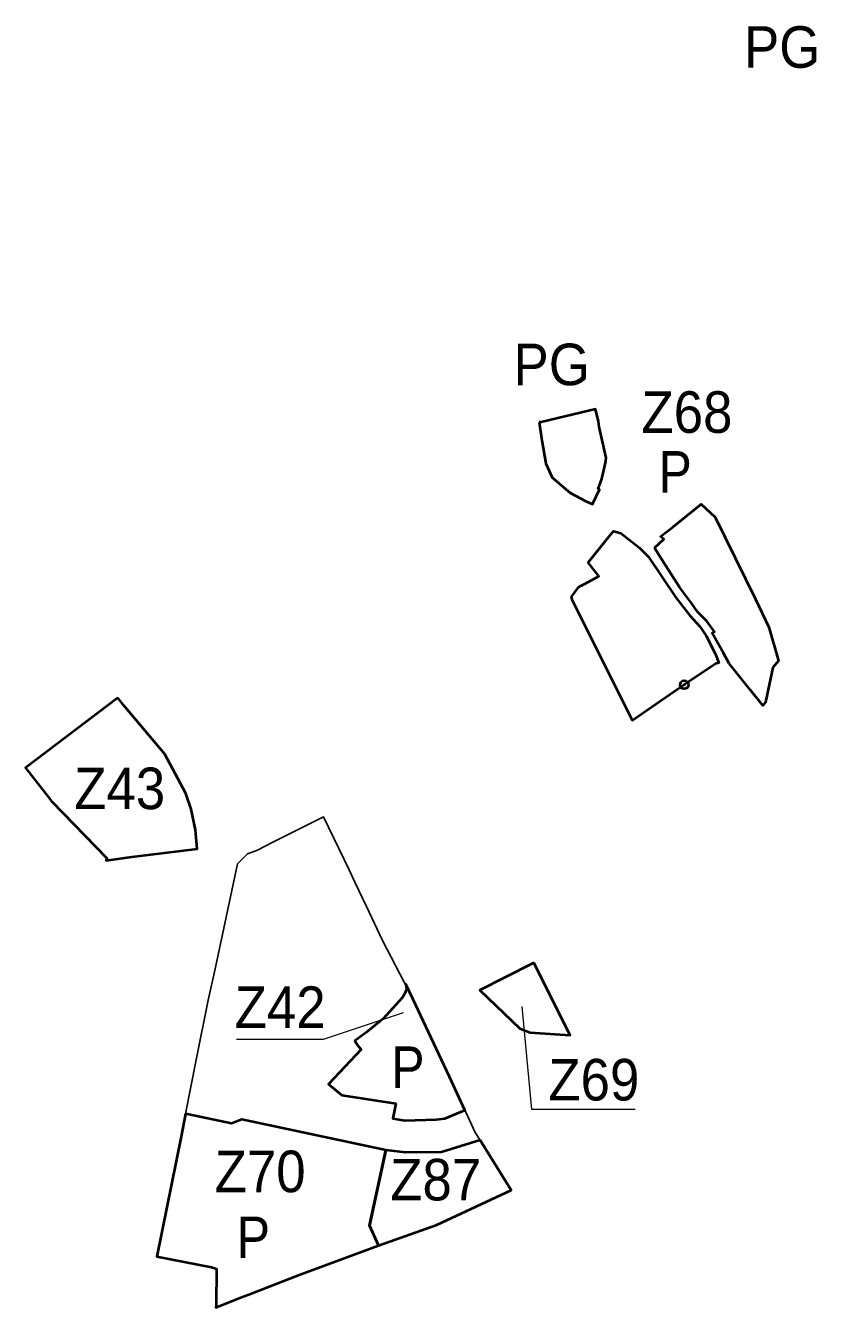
# Model space of a CAD drawing. Extents: x -650276 to -642489, y -1074311 to -1066658.
# Drawn here: x -647280 to -646824, y -1071533 to -1070793 of the extents above; entities that cross this region are included whole.
import ezdxf

# ---------------------------------------------------------------- set-up
doc = ezdxf.new("R2010")
doc.units = 0
doc.header["$LTSCALE"] = 9.6
doc.header["$PDMODE"] = 32
doc.header["$PDSIZE"] = 4.8
for name, color, linetype, lineweight in [('42', 7, 'Continuous', 25), ('44', 7, 'Continuous', 40), ('45', 7, 'Continuous', 40), ('46', 7, 'Continuous', 13), ('60', 7, 'Continuous', 35)]:
    doc.layers.add(name, color=color, linetype=linetype, lineweight=lineweight)

msp = doc.modelspace()

# ---------------------------------------------------------------- linework, layer by layer
at = {"layer": '42'}
msp.add_lwpolyline([(-647187.85, -1071421.58), (-647190.4, -1071434.75), (-647204.42, -1071504.1), (-647172.74, -1071510.15), (-647170.01, -1071511.22), (-647170.18, -1071532.22), (-647170.23, -1071533.44), (-647155.58, -1071527.62), (-647151.28, -1071525.99), (-647123.17, -1071515.01), (-647104.47, -1071508.08), (-647076.46, -1071497.69), (-647042.78, -1071485.76), (-647022.81, -1071476.61), (-646999.77, -1071465.81), (-647017.7, -1071436.79), (-647020.52, -1071432.42), (-647030.23, -1071411.53), (-647035.47, -1071400.31), (-647056.48, -1071355.32), (-647073.98, -1071321.53), (-647083.22, -1071302), (-647090, -1071287.89), (-647093.39, -1071280.83), (-647108.16, -1071250.08), (-647130.76, -1071261.49), (-647137.84, -1071265.06), (-647146.3, -1071269.33), (-647152.09, -1071271.47), (-647157.83, -1071277.35), (-647168.91, -1071329.88), (-647170.63, -1071337.91), (-647174.73, -1071356.1), (-647181.75, -1071390.51)], close=True, dxfattribs=at)
at = {"layer": '44'}
msp.add_line((-647081.488, -1071486.251), (-647076.46, -1071497.69), dxfattribs=at)
for points in [[(-647017.7, -1071436.79), (-647040.089, -1071443.76), (-647060.812, -1071444.006), (-647072.11, -1071442.6), (-647081.488, -1071486.251)], [(-647076.46, -1071497.69), (-647042.78, -1071485.76), (-647022.81, -1071476.61), (-646999.77, -1071465.81), (-647017.7, -1071436.79)]]:
    msp.add_lwpolyline(points, dxfattribs=at)
at = {"layer": '45'}
for points in [[(-646983.66, -1071022.3), (-646982.08, -1071032.76), (-646979.75, -1071046.19), (-646976.03, -1071054.29), (-646965.69, -1071063.05), (-646956.66, -1071067.91), (-646952.75, -1071069.62), (-646948.83, -1071061.12), (-646949.48, -1071060.79), (-646947.41, -1071054.95), (-646945.38, -1071045.82), (-646944.88, -1071042.78), (-646948.89, -1071024.84), (-646949.39, -1071021.83), (-646951.06, -1071014.78), (-646955.09, -1071015.67), (-646982.41, -1071022.23)], [(-646983.66, -1071022.3), (-646982.08, -1071032.76), (-646979.75, -1071046.19), (-646976.03, -1071054.29), (-646965.69, -1071063.05), (-646956.66, -1071067.91), (-646952.75, -1071069.62), (-646948.83, -1071061.12), (-646949.48, -1071060.79), (-646947.41, -1071054.95), (-646945.38, -1071045.82), (-646944.88, -1071042.78), (-646948.89, -1071024.84), (-646949.39, -1071021.83), (-646951.06, -1071014.78), (-646955.09, -1071015.67), (-646982.41, -1071022.23)], [(-646917.04, -1071094.75), (-646911.58, -1071089.9), (-646913.49, -1071088.22), (-646906.17, -1071082.72), (-646890.12, -1071069.67), (-646881.89, -1071077.03), (-646858.769, -1071124.46), (-646850.93, -1071140.54), (-646845.39, -1071159.98), (-646848.58, -1071163.95), (-646852.86, -1071183.98), (-646854.49, -1071185.87), (-646861.58, -1071177.05), (-646873.89, -1071161.58), (-646877.226, -1071155.611), (-646883.63, -1071144.15), (-646882.37, -1071143.39), (-646886.78, -1071137.25), (-646892.11, -1071131.81), (-646895.56, -1071126.84), (-646902.62, -1071117.58), (-646910.53, -1071105.18)], [(-646917.04, -1071094.75), (-646911.58, -1071089.9), (-646913.49, -1071088.22), (-646906.17, -1071082.72), (-646890.12, -1071069.67), (-646881.89, -1071077.03), (-646858.769, -1071124.46), (-646850.93, -1071140.54), (-646845.39, -1071159.98), (-646848.58, -1071163.95), (-646852.86, -1071183.98), (-646854.49, -1071185.87), (-646861.58, -1071177.05), (-646873.89, -1071161.58), (-646877.226, -1071155.611), (-646883.63, -1071144.15), (-646882.37, -1071143.39), (-646886.78, -1071137.25), (-646892.11, -1071131.81), (-646895.56, -1071126.84), (-646902.62, -1071117.58), (-646910.53, -1071105.18)], [(-646921.668, -1071098.861), (-646920.54, -1071099.98), (-646904.64, -1071123.54), (-646896.62, -1071133.93), (-646890.59, -1071140.39), (-646887.07, -1071145.66), (-646881.97, -1071155.84), (-646879.91, -1071161.24), (-646881.68, -1071161.83), (-646899.85, -1071173.89), (-646929.64, -1071194.58), (-646955.2, -1071143.67), (-646964.43, -1071125.3), (-646964.99, -1071123.18), (-646960.72, -1071117.25), (-646957.26, -1071115.61), (-646949.12, -1071111.22), (-646955.39, -1071103.23), (-646943.47, -1071088.69), (-646940.67, -1071085.15), (-646936.51, -1071086.33), (-646925.88, -1071094.68)], [(-646921.668, -1071098.861), (-646920.54, -1071099.98), (-646904.64, -1071123.54), (-646896.62, -1071133.93), (-646890.59, -1071140.39), (-646887.07, -1071145.66), (-646881.97, -1071155.84), (-646879.91, -1071161.24), (-646881.68, -1071161.83), (-646899.85, -1071173.89), (-646929.64, -1071194.58), (-646955.2, -1071143.67), (-646964.43, -1071125.3), (-646964.99, -1071123.18), (-646960.72, -1071117.25), (-646957.26, -1071115.61), (-646949.12, -1071111.22), (-646955.39, -1071103.23), (-646943.47, -1071088.69), (-646940.67, -1071085.15), (-646936.51, -1071086.33), (-646925.88, -1071094.68)], [(-647226.895, -1071181.511), (-647280.14, -1071221.92), (-647268.52, -1071236.78), (-647265.15, -1071241.1), (-647233.34, -1071274.07), (-647233.64, -1071275.42), (-647218.75, -1071273.32), (-647181.12, -1071268.66), (-647181.99, -1071257.66), (-647184.58, -1071245.67), (-647187.68, -1071236.74), (-647192.29, -1071228.1), (-647199.82, -1071213.98), (-647223.46, -1071185.83)], [(-647226.895, -1071181.511), (-647280.14, -1071221.92), (-647268.52, -1071236.78), (-647265.15, -1071241.1), (-647233.34, -1071274.07), (-647233.64, -1071275.42), (-647218.75, -1071273.32), (-647181.12, -1071268.66), (-647181.99, -1071257.66), (-647184.58, -1071245.67), (-647187.68, -1071236.74), (-647192.29, -1071228.1), (-647199.82, -1071213.98), (-647223.46, -1071185.83)], [(-646986.69, -1071334.53), (-647003.37, -1071342.99), (-647017.93, -1071350.33), (-646994.85, -1071372.49), (-646988.77, -1071374.77), (-646965.74, -1071376.18)], [(-646986.69, -1071334.53), (-647003.37, -1071342.99), (-647017.93, -1071350.33), (-646994.85, -1071372.49), (-646988.77, -1071374.77), (-646965.74, -1071376.18)], [(-647056.48, -1071355.32), (-647060.6, -1071346.87), (-647060.22, -1071349.87), (-647061.4, -1071352.51), (-647062.78, -1071354.77), (-647073.68, -1071366.75), (-647075.25, -1071368.01), (-647083.48, -1071374.62), (-647090.04, -1071379.44), (-647088.57, -1071381.97), (-647086.45, -1071384.59), (-647105.2, -1071404.54), (-647097.5, -1071410.96), (-647066.35, -1071415.79), (-647068.162, -1071424.298), (-647061.23, -1071425.434), (-647043.137, -1071424.978), (-647038.119, -1071424.37), (-647026.472, -1071419.614), (-647035.47, -1071400.31)], [(-647056.48, -1071355.32), (-647060.6, -1071346.87), (-647060.22, -1071349.87), (-647061.4, -1071352.51), (-647062.78, -1071354.77), (-647073.68, -1071366.75), (-647075.25, -1071368.01), (-647083.48, -1071374.62), (-647090.04, -1071379.44), (-647088.57, -1071381.97), (-647086.45, -1071384.59), (-647105.2, -1071404.54), (-647097.5, -1071410.96), (-647066.35, -1071415.79), (-647068.162, -1071424.298), (-647061.23, -1071425.434), (-647043.137, -1071424.978), (-647038.119, -1071424.37), (-647026.472, -1071419.614), (-647035.47, -1071400.31)], [(-647072.11, -1071442.6), (-647155.36, -1071425), (-647161.2, -1071427.33), (-647185.99, -1071421.98), (-647187.85, -1071421.58), (-647190.4, -1071434.75), (-647204.42, -1071504.1), (-647172.74, -1071510.15), (-647170.01, -1071511.22), (-647170.18, -1071532.22), (-647170.23, -1071533.44), (-647155.58, -1071527.62), (-647151.28, -1071525.99), (-647123.17, -1071515.01), (-647104.47, -1071508.08), (-647076.46, -1071497.69), (-647081.488, -1071486.251)], [(-647072.11, -1071442.6), (-647155.36, -1071425), (-647161.2, -1071427.33), (-647185.99, -1071421.98), (-647187.85, -1071421.58), (-647190.4, -1071434.75), (-647204.42, -1071504.1), (-647172.74, -1071510.15), (-647170.01, -1071511.22), (-647170.18, -1071532.22), (-647170.23, -1071533.44), (-647155.58, -1071527.62), (-647151.28, -1071525.99), (-647123.17, -1071515.01), (-647104.47, -1071508.08), (-647076.46, -1071497.69), (-647081.488, -1071486.251)]]:
    msp.add_lwpolyline(points, close=True, dxfattribs=at)
msp.add_point((-646899.85, -1071173.89), dxfattribs=at)
at = {"layer": '46'}
for points in [[(-646928.092, -1071419.173), (-646987.822, -1071419.173), (-646993.397, -1071359.705)], [(-646928.092, -1071419.173), (-646987.822, -1071419.173), (-646993.397, -1071359.705)], [(-647158.414, -1071378.568), (-647108.186, -1071378.568), (-647061.975, -1071363.219)], [(-647158.414, -1071378.568), (-647108.186, -1071378.568), (-647061.975, -1071363.219)]]:
    msp.add_lwpolyline(points, dxfattribs=at)

# ---------------------------------------------------------------- texts
at = {"layer": '44', "width": 0.95}
msp.add_text('Z87', height=24, dxfattribs=at).set_placement((-647069.618, -1071471.685))
msp.add_text('Z87', height=24, dxfattribs=at).set_placement((-647069.618, -1071471.685))
at = {"layer": '46', "width": 0.95}
for s, p in [('Z68', (-646924.523, -1071028.411)), ('Z68', (-646924.523, -1071028.411)), ('Z43', (-647252.085, -1071245.723)), ('Z43', (-647252.085, -1071245.723)), ('Z42', (-647159.441, -1071372.08)), ('Z42', (-647159.441, -1071372.08)), ('Z69', (-646978.284, -1071413.97)), ('Z69', (-646978.284, -1071413.97)), ('Z70', (-647171.004, -1071466.914)), ('Z70', (-647171.004, -1071466.914))]:
    msp.add_text(s, height=24, dxfattribs=at).set_placement(p)
at = {"layer": '60'}
for s, width, p in [('PG', 0.95, (-646865.3, -1070817.6)), ('PG', 0.95, (-646998.384, -1071000.904)), ('PG', 0.95, (-646998.384, -1071000.904)), ('P', 0.9, (-646914.697, -1071062.931)), ('P', 0.9, (-646914.697, -1071062.931)), ('P', 0.9, (-647069.021, -1071406.74)), ('P', 0.9, (-647069.021, -1071406.74)), ('P', 0.9, (-647158.268, -1071504.971)), ('P', 0.9, (-647158.268, -1071504.971))]:
    msp.add_text(s, height=24, dxfattribs=dict(at, width=width)).set_placement(p)

doc.saveas('drawing.dxf')
